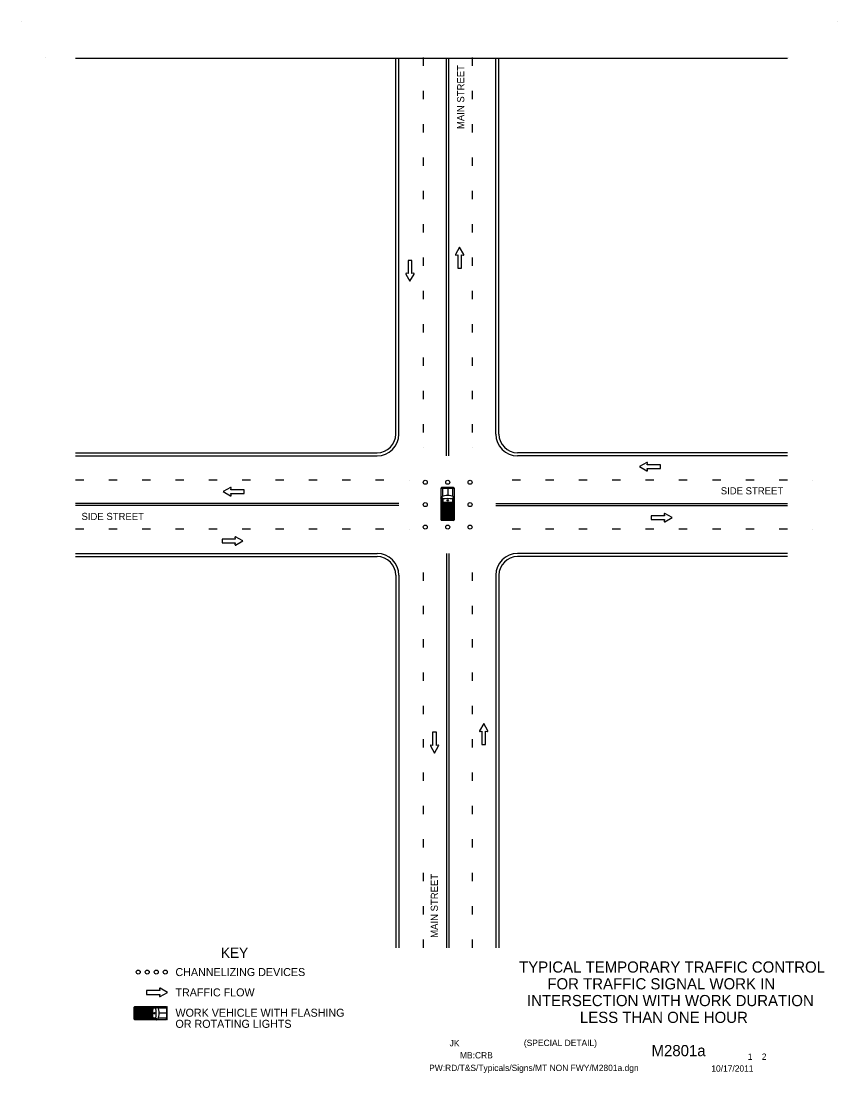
# Model space of a CAD drawing. Extents: x 376 to 2016, y -51 to 984.
# Drawn here: x 376 to 1179, y -51 to 984 of the extents above; entities that cross this region are included whole.
import ezdxf

# ---------------------------------------------------------------- set-up
doc = ezdxf.new("R2010")
doc.units = 0
for name, color, linetype in [('Border', 7, 'Continuous'), ('BORDER_SIGNAL_WO', 7, 'Continuous'), ('Level 21', 7, 'Continuous'), ('Level 42', 7, 'Continuous'), ('MT_SCRATCH_LEVEL_E', 7, 'Continuous'), ('PAVT_EDGE_EX', 7, 'Continuous'), ('PAVT_MRKGS_EX', 7, 'Continuous'), ('TRAFFIC_SIGNS_PR', 7, 'Continuous'), ('TYPICAL_EX', 7, 'Continuous'), ('TYPICAL_TEXT_DIMEN_EX', 7, 'Continuous'), ('TYPICAL_TEXT_DIMEN_PR', 7, 'Continuous')]:
    doc.layers.add(name, color=color, linetype=linetype)

# ---------------------------------------------------------------- blocks, each defined once
blk = doc.blocks.new('BA')
at = {"layer": 'TRAFFIC_SIGNS_PR'}
blk.add_circle((0, 0), 0.656, dxfattribs=at)
blk = doc.blocks.new('SKIP')
at = {"layer": 'Level 21'}
for p, q in [((8.2, 0), (0, 0)), ((41, 0), (32.8, 0)), ((73.8, 0), (65.6, 0)), ((106.6, 0), (98.4, 0)), ((139.4, 0), (131.2, 0)), ((164, 0), (164, 0))]:
    blk.add_line(p, q, dxfattribs=at)
blk = doc.blocks.new('TRKRDM')
at = {"layer": 'TYPICAL_EX'}
for p, q in [((-1.09, 1.94), (-0.82, 1.94)), ((-1.09, 0.36), (-1.09, 1.94)), ((-1.08, 1.96), (1.08, 1.96)), ((0.98, 2.06), (-0.99, 2.06)), ((-0.82, 1.95), (-0.81, 1.96)), ((-0.82, 1.95), (0.81, 1.95)), ((-0.82, 1.95), (-0.82, 0.61)), ((0, 1.95), (0, 0.67)), ((0.81, 1.95), (0.8, 1.96)), ((0.81, 1.95), (0.81, 0.61)), ((1.09, 1.94), (0.82, 1.94)), ((1.08, 1.94), (1.08, 0.36)), ((-1.09, -3.25), (-1.09, 0.29)), ((-0.8, 0.19), (-1.01, 0.56)), ((-0.82, 0.18), (-1.01, 0.5)), ((-1.01, 0.5), (-1.01, 0.36)), ((-1.01, 0.29), (-1.01, -0.33)), ((-0.82, 0.18), (-0.82, -0.33)), ((-0.8, 0.18), (-0.8, -0.33)), ((0.81, 0.19), (1, 0.56)), ((0.81, 0.18), (0.81, -0.33)), ((0.84, 0.18), (1, 0.49)), ((0.84, 0.18), (0.84, -0.33)), ((1, 0.49), (1, 0.36)), ((1, 0.29), (1, -0.33)), ((1.08, 0.29), (1.08, -3.25)), ((-1.09, -0.48), (1.08, -0.48)), ((-0.82, -0.33), (-1.01, -0.33)), ((-0.99, -0.48), (-0.8, -0.39)), ((-0.99, -0.48), (-0.99, -3.25)), ((-0.87, -0.48), (-0.87, -1.81)), ((-0.8, -0.33), (-0.8, -0.33)), ((-0.74, -0.48), (-0.74, -3.18)), ((-0.62, -0.48), (-0.62, -3.18)), ((-0.5, -0.48), (-0.5, -3.18)), ((-0.37, -0.48), (-0.37, -3.18)), ((-0.25, -0.48), (-0.25, -3.18)), ((-0.13, -0.48), (-0.13, -3.18)), ((-0.01, -0.48), (-0.01, -3.18)), ((0.12, -0.48), (0.12, -3.18)), ((0.24, -0.48), (0.24, -3.18)), ((0.36, -0.48), (0.36, -3.18)), ((0.49, -0.48), (0.49, -3.18)), ((0.61, -0.48), (0.61, -3.18)), ((0.73, -0.48), (0.73, -3.18)), ((0.98, -0.48), (0.81, -0.39)), ((0.84, -0.33), (1, -0.33)), ((0.86, -0.48), (0.86, -1.81)), ((0.98, -0.48), (0.98, -3.25)), ((-1.09, -3.25), (1.08, -3.25)), ((-0.9, -1.8), (-0.99, -1.8)), ((-0.99, -2.88), (-0.9, -2.88)), ((-0.99, -3.18), (0.98, -3.18)), ((0.98, -3.35), (-0.99, -3.35)), ((-0.87, -2.87), (-0.87, -3.18)), ((-0.8, -2.78), (-0.8, -1.9)), ((0.79, -2.78), (0.79, -1.9)), ((0.86, -2.87), (0.86, -3.18)), ((0.89, -1.8), (0.98, -1.8)), ((0.98, -2.88), (0.89, -2.88))]:
    blk.add_line(p, q, dxfattribs=at)
for points in [[(-1.1, 0.36), (-0.96, 0.36), (-0.96, 0.29), (-1.1, 0.29)], [(1.1, 0.36), (0.95, 0.36), (0.95, 0.29), (1.1, 0.29)]]:
    blk.add_lwpolyline(points, close=True, dxfattribs=at)
blk.add_circle((0.01, -0.04), 0.118, dxfattribs=at)
for centre, radius, start, end in [((-0.99, 1.96), 0.0984, 90, 180), ((0.98, 1.96), 0.0984, 0, 90), ((0, -2.22), 2.95, 70.1094, 109.9771), ((-0.99, -3.25), 0.0984, 180, 270), ((-0.9, -1.9), 0.0984, 0, 90), ((-0.9, -2.78), 0.0984, 270, 0), ((0.89, -1.9), 0.0984, 90, 180), ((0.89, -2.78), 0.0984, 180, 270), ((0.98, -3.25), 0.0984, 270, 0)]:
    blk.add_arc(centre, radius, start, end, dxfattribs=at)
for centre, major_axis, start_param, end_param in [((0.01, -4.68), (5.41, 0), 1.421824, 1.719865), ((0, -4.69), (5.41, 0), 1.421875, 1.71941), ((0.01, 9.49), (10.83, 0), 4.638102, 4.786676), ((0, 9.43), (10.83, 0), 4.638102, 4.786676)]:
    blk.add_ellipse(centre, major_axis=major_axis, ratio=0.909091, start_param=start_param, end_param=end_param, dxfattribs=at)
blk = doc.blocks.new('BAS')
at = {"layer": 'TRAFFIC_SIGNS_PR'}
for centre in [(2.95, 0), (5.91, 0), (8.86, 0)]:
    blk.add_circle(centre, 0.656, dxfattribs=at)
at = {"layer": 'TRAFFIC_SIGNS_PR', "xscale": 0.9999996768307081, "yscale": 0.9999996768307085, "rotation": 166.2133425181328}
blk.add_blockref('BA', (0, 0), dxfattribs=at)
blk = doc.blocks.new('TFA')
at = {"layer": 'MT_SCRATCH_LEVEL_E'}
for p, q in [((-3.33, 0.81), (-9.13, 0.81)), ((-9.13, 0.81), (-9.13, -0.83)), ((-3.47, 1.59), (-3.33, 0.81)), ((0, 0), (-3.17, 1.8)), ((-3.17, -1.81), (0, 0)), ((-9.13, -0.83), (-3.33, -0.83)), ((-3.33, -0.83), (-3.47, -1.6))]:
    blk.add_line(p, q, dxfattribs=at)
for centre, start, end in [((-3.27, 1.62), 60.4248, 189.9638), ((-3.27, -1.63), 170.0362, 299.7731)]:
    blk.add_arc(centre, 0.202, start, end, dxfattribs=at)

msp = doc.modelspace()

# ---------------------------------------------------------------- linework, layer by layer
at = {"layer": 'Border'}
for p, q in [((376.1, 983.6), (376.1, 983.6)), ((1179.2, 983.6), (1179.2, 983.6)), ((399.9, 948), (399.9, 948)), ((429.5, 947.2), (1129.5, 947.2)), ((1130.3, 948), (1130.3, 948))]:
    msp.add_line(p, q, dxfattribs=at)
at = {"layer": 'Level 21'}
for p, q in [((771.5, 564.3), (771.5, 564.3)), ((819.5, 564.3), (819.5, 564.3)), ((990.1, 532), (990.1, 532)), ((990.1, 484), (990.1, 484))]:
    msp.add_line(p, q, dxfattribs=at)
at = {"layer": 'PAVT_EDGE_EX'}
for p, q in [((744.5, 577.3), (744.5, 947.2)), ((845.8, 577.3), (845.8, 947.2)), ((429.5, 559), (726.2, 559)), ((1129.5, 559), (864.2, 559)), ((429.5, 457), (726.2, 457)), ((1129.5, 457), (864.2, 457)), ((744.5, 438.6), (744.5, 72.2)), ((845.8, 438.6), (845.8, 72.2))]:
    msp.add_line(p, q, dxfattribs=at)
for centre, start, end in [((726.2, 577.3), 270, 0), ((864.2, 577.3), 180, 270), ((726.2, 438.6), 0, 90), ((864.2, 438.6), 90, 180)]:
    msp.add_arc(centre, 18.3, start, end, dxfattribs=at)
at = {"layer": 'PAVT_MRKGS_EX'}
for p, q in [((747.5, 577.3), (747.5, 947.2)), ((771.5, 947.9), (771.5, 939.7)), ((794.5, 556), (794.5, 947.2)), ((796.5, 556), (796.5, 947.2)), ((819.5, 947.9), (819.5, 939.7)), ((842.8, 577.3), (842.8, 947.2)), ((771.5, 915), (771.5, 906.8)), ((819.5, 915), (819.5, 906.8)), ((429.5, 556), (726.2, 556)), ((1129.5, 556), (864.2, 556)), ((867, 532), (858.8, 532)), ((899.8, 532), (891.6, 532)), ((932.6, 532), (924.4, 532)), ((965.5, 532), (957.3, 532)), ((747.5, 509), (429.5, 509)), ((747.5, 507), (429.5, 507)), ((842.8, 509), (1129.5, 509)), ((842.8, 507), (1129.5, 507)), ((867, 484), (858.8, 484)), ((899.8, 484), (891.6, 484)), ((932.6, 484), (924.4, 484)), ((965.5, 484), (957.3, 484)), ((429.5, 460), (726.2, 460)), ((794.5, 460), (794.5, 72.2)), ((796.5, 460), (796.5, 72.2)), ((1129.5, 460), (864.2, 460)), ((747.5, 438.6), (747.5, 72.2)), ((771.5, 441.3), (771.5, 433.1)), ((819.5, 441.3), (819.5, 433.1)), ((842.8, 438.6), (842.8, 72.2)), ((771.5, 408.4), (771.5, 400.2)), ((819.5, 408.4), (819.5, 400.2))]:
    msp.add_line(p, q, dxfattribs=at)
for centre, start, end in [((726.2, 577.3), 270, 0), ((864.2, 577.3), 180, 270), ((726.2, 438.6), 0, 90), ((864.2, 438.6), 90, 180)]:
    msp.add_arc(centre, 21.3, start, end, dxfattribs=at)

# ---------------------------------------------------------------- block references
at = {"layer": 'Level 42', "xscale": 3, "yscale": 3, "rotation": 90}
for p in [(773.5, 530), (795.5, 530), (817.5, 530), (773.5, 508), (817.5, 508), (773.5, 485.9), (795.5, 485.9), (817.5, 485.9)]:
    msp.add_blockref('BA', p, dxfattribs=at)
at = {"layer": 'PAVT_MRKGS_EX', "rotation": 90.00000000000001}
for p in [(771.5, 742.8), (819.5, 742.8), (771.5, 578.8), (819.5, 578.8), (771.5, 236.2), (819.5, 236.2), (771.5, 72.2), (819.5, 72.2)]:
    msp.add_blockref('SKIP', p, dxfattribs=at)
at = {"layer": 'PAVT_MRKGS_EX', "xscale": 2.25, "yscale": 2.25}
for p, rotation in [((807.2, 761.2), 90), ((758.4, 727.7), -90.00000000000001), ((984.2, 545.4), 180), ((574.9, 520.8), 180), ((830.9, 292.7), 90), ((782.6, 263.7), -90.00000000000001)]:
    msp.add_blockref('TFA', p, dxfattribs=dict(at, rotation=rotation))
at = {"layer": 'PAVT_MRKGS_EX'}
for p in [(429.5, 532), (593.5, 532), (990.1, 532), (429.5, 484), (593.5, 484), (990.1, 484)]:
    msp.add_blockref('SKIP', p, dxfattribs=at)
at = {"layer": 'PAVT_MRKGS_EX', "xscale": 2.25, "yscale": 2.25}
for p in [(1016.2, 495.2), (594.2, 472.3)]:
    msp.add_blockref('TFA', p, dxfattribs=at)
at = {"layer": 'TYPICAL_TEXT_DIMEN_EX'}
for name, p, xscale, yscale in [('TRKRDM', (795.5, 512.5), 6, 6), ('BAS', (491.3, 48.2), 3, 3)]:
    msp.add_blockref(name, p, dxfattribs=dict(at, xscale=xscale, yscale=yscale))
at = {"layer": 'TYPICAL_TEXT_DIMEN_EX', "xscale": 6, "yscale": 6, "rotation": -89.99999999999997}
msp.add_blockref('TRKRDM', (507.5, 7.8), dxfattribs=at)
at = {"layer": 'TYPICAL_TEXT_DIMEN_PR', "xscale": 2.25, "yscale": 2.25}
msp.add_blockref('TFA', (519.9, 28.2), dxfattribs=at)

# ---------------------------------------------------------------- texts
at = {"layer": 'BORDER_SIGNAL_WO'}
for s, height, p in [('TYPICAL TEMPORARY TRAFFIC CONTROL', 11, (865.7, 47.7)), ('FOR TRAFFIC SIGNAL WORK IN', 11, (893.5, 31.2)), ('INTERSECTION WITH WORK DURATION', 11, (873.5, 14.7)), ('LESS THAN ONE HOUR', 11, (925.5, -1.8)), ('JK          ', 6.2, (797.4, -24.8)), ('  (SPECIAL DETAIL)  ', 6.2, (865.8, -24.5)), ('MB:CRB', 6.2, (807.6, -36.7)), ('    M2801a   ', 11, (979.6, -34.5)), (' 1    2 ', 6.2, (1088.2, -38.1)), ('PW:RD/T&S/Typicals/Signs/MT NON FWY/M2801a.dgn ', 6.2, (777.3, -49.1)), ('10/17/2011', 6.2, (1054.7, -49.7))]:
    msp.add_text(s, height=height, dxfattribs=at).set_placement(p)
at = {"layer": 'TYPICAL_TEXT_DIMEN_EX'}
for p in [(811.8, 877.4), (785.9, 81.9)]:
    msp.add_text('MAIN STREET', height=7, rotation=90, dxfattribs=at).set_placement(p)
for s, height, p in [('SIDE STREET', 7, (1064, 518.1)), ('SIDE STREET', 7, (435.5, 492.9)), ('KEY', 10, (572.6, 62.2)), ('CHANNELIZING DEVICES', 7.874, (527.9, 44.3)), ('TRAFFIC FLOW', 7.874, (527.9, 24.3)), ('WORK VEHICLE WITH FLASHING', 7.874, (527.9, 4.3)), ('OR ROTATING LIGHTS', 7.874, (527.9, -6.6))]:
    msp.add_text(s, height=height, dxfattribs=at).set_placement(p)

doc.saveas('drawing.dxf')
